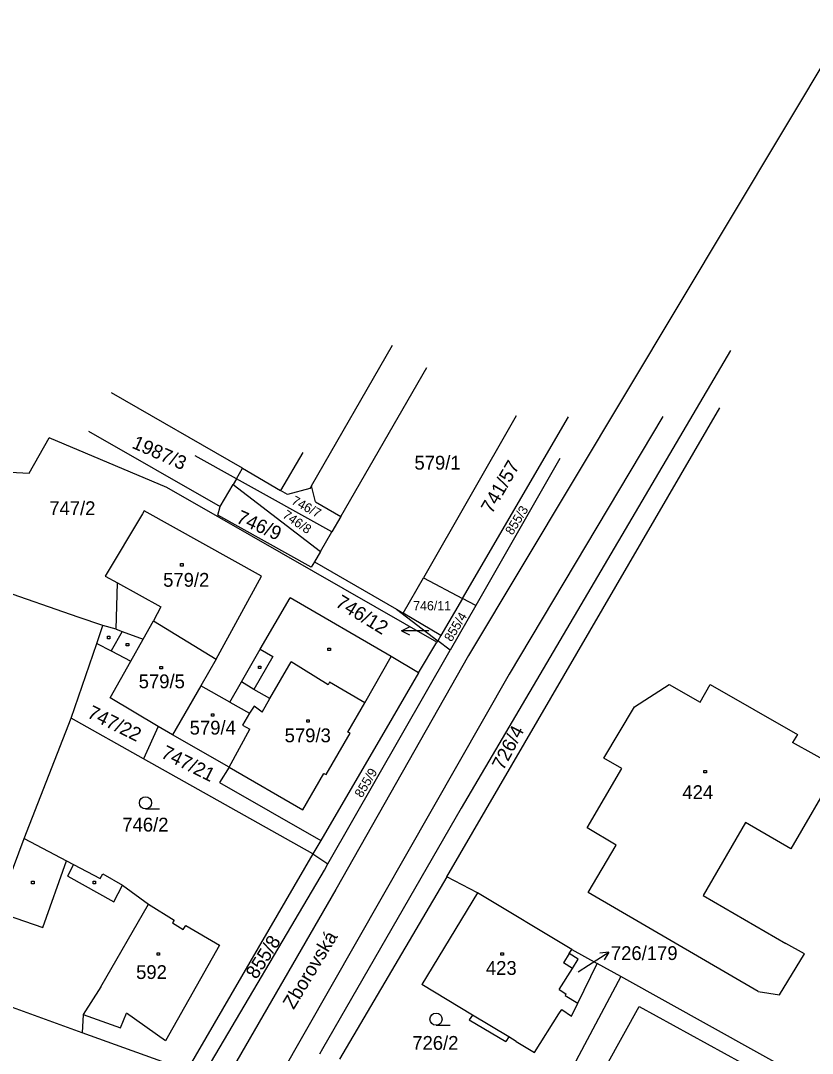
# Model space of a CAD drawing. Extents: x -711879 to -711361, y -1048782 to -1048177.
# Drawn here: x -711584.5 to -711487, y -1048304.3 to -1048177.1 of the extents above; entities that cross this region are included whole.
import ezdxf

# ---------------------------------------------------------------- set-up
doc = ezdxf.new("R2010")
doc.units = 0
for name, color, linetype in [('Vrstva 1', 7, 'Continuous'), ('Vrstva 13', 7, 'Continuous'), ('Vrstva 14', 7, 'Continuous'), ('Vrstva 15', 7, 'Continuous'), ('Vrstva 16', 7, 'Continuous'), ('Vrstva 2', 7, 'Continuous'), ('Vrstva 23', 7, 'Continuous'), ('Vrstva 25', 7, 'Continuous'), ('Vrstva 38', 7, 'Continuous'), ('Vrstva 46', 7, 'Continuous')]:
    doc.layers.add(name, color=color, linetype=linetype)

msp = doc.modelspace()

# ---------------------------------------------------------------- linework, layer by layer
at = {"layer": 'Vrstva 1'}
for p, q in [((-711482.5, -1048177.05), (-711529.35, -1048255.3)), ((-711548.71, -1048234.38), (-711538.72, -1048217.07)), ((-711497.07, -1048217.69), (-711530.26, -1048274.12)), ((-711545.09, -1048238.16), (-711534.5, -1048219.82)), ((-711557.2, -1048232.23), (-711573.32, -1048222.93)), ((-711523.47, -1048225.77), (-711534.89, -1048245.72)), ((-711532.03, -1048282.6), (-711498.38, -1048224.76)), ((-711530.09, -1048248.27), (-711517.02, -1048225.89)), ((-711505.42, -1048225.86), (-711524.36, -1048257.61)), ((-711583.46, -1048232.83), (-711581.03, -1048228.47)), ((-711566.51, -1048234.58), (-711581.03, -1048228.47)), ((-711576.16, -1048227.66), (-711559.94, -1048236.95)), ((-711557.94, -1048233.51), (-711563.01, -1048230.69)), ((-711549.75, -1048230.27), (-711552.5, -1048234.96)), ((-711518.11, -1048231.02), (-711528.46, -1048249.13)), ((-711593.81, -1048232.28), (-711583.46, -1048232.83)), ((-711557.94, -1048233.51), (-711557.2, -1048232.23)), ((-711557.2, -1048232.23), (-711552.5, -1048234.96)), ((-711557.94, -1048233.51), (-711558.36, -1048234.23)), ((-711546.19, -1048240.06), (-711557.94, -1048233.51)), ((-711559.98, -1048238.33), (-711566.51, -1048234.58)), ((-711559.94, -1048236.95), (-711558.36, -1048234.23)), ((-711558.36, -1048234.23), (-711547.58, -1048242.47)), ((-711548.91, -1048234.73), (-711551.64, -1048235.46)), ((-711548.71, -1048234.38), (-711548.91, -1048234.73)), ((-711548.21, -1048236.36), (-711548.71, -1048234.38)), ((-711551.64, -1048235.46), (-711552.5, -1048234.96)), ((-711560.23, -1048238.01), (-711559.94, -1048236.95)), ((-711548.21, -1048236.36), (-711545.09, -1048238.16)), ((-711569.52, -1048237.85), (-711574.1, -1048245.52)), ((-711569.3, -1048237.49), (-711569.52, -1048237.85)), ((-711554.84, -1048245.54), (-711569.3, -1048237.49)), ((-711548.72, -1048244.4), (-711560.23, -1048238.01)), ((-711533.26, -1048253.68), (-711559.98, -1048238.33)), ((-711545.09, -1048238.16), (-711546.19, -1048240.06)), ((-711547.58, -1048242.47), (-711546.19, -1048240.06)), ((-711547.58, -1048242.47), (-711548.33, -1048243.76)), ((-711548.33, -1048243.76), (-711548.72, -1048244.4)), ((-711548.33, -1048243.76), (-711538.23, -1048249.6)), ((-711574.1, -1048245.52), (-711572.59, -1048246.35)), ((-711560.45, -1048255.74), (-711554.84, -1048245.54)), ((-711537.39, -1048250.09), (-711534.89, -1048245.72)), ((-711534.89, -1048245.72), (-711530.09, -1048248.27)), ((-711577.43, -1048250.58), (-711587.36, -1048247.11)), ((-711572.76, -1048252.07), (-711572.59, -1048246.35)), ((-711572.59, -1048246.35), (-711567.25, -1048249.29)), ((-711555, -1048254.52), (-711551.34, -1048248.21)), ((-711538.88, -1048255.43), (-711551.34, -1048248.21)), ((-711530.09, -1048248.27), (-711532.77, -1048252.85)), ((-711528.46, -1048249.13), (-711530.09, -1048248.27)), ((-711567.25, -1048249.29), (-711568.14, -1048251.02)), ((-711538.23, -1048249.6), (-711533.14, -1048253.48)), ((-711538.23, -1048249.6), (-711537.39, -1048250.09)), ((-711532.77, -1048252.85), (-711537.39, -1048250.09)), ((-711528.46, -1048249.13), (-711531.61, -1048254.65)), ((-711574.38, -1048251.61), (-711577.43, -1048250.58)), ((-711568.14, -1048251.02), (-711560.45, -1048255.74)), ((-711575.14, -1048253.81), (-711574.38, -1048251.61)), ((-711572.76, -1048252.07), (-711574.38, -1048251.61)), ((-711578.31, -1048263.02), (-711575.14, -1048253.81)), ((-711575.14, -1048253.81), (-711573.37, -1048254.73)), ((-711535.51, -1048257.44), (-711533.26, -1048253.68)), ((-711533.14, -1048253.48), (-711533.26, -1048253.68)), ((-711532.77, -1048252.85), (-711533.14, -1048253.48)), ((-711531.61, -1048254.65), (-711533.14, -1048253.48)), ((-711573.37, -1048254.73), (-711570.94, -1048256)), ((-711557.32, -1048258.56), (-711555, -1048254.52)), ((-711546.67, -1048281), (-711531.61, -1048254.65)), ((-711573.48, -1048260.53), (-711570.94, -1048256)), ((-711560.45, -1048255.74), (-711562.34, -1048259.04)), ((-711529.35, -1048255.3), (-711545.71, -1048284.16)), ((-711535.51, -1048257.44), (-711538.88, -1048255.43)), ((-711524.36, -1048257.61), (-711555.05, -1048311.45)), ((-711535.51, -1048257.44), (-711538.77, -1048263.01)), ((-711562.34, -1048259.04), (-711565.8, -1048265.09)), ((-711558.75, -1048261.05), (-711562.34, -1048259.04)), ((-711558.75, -1048261.05), (-711557.32, -1048258.56)), ((-711508.91, -1048261.64), (-711504.62, -1048258.86)), ((-711504.62, -1048258.86), (-711500.82, -1048261.06)), ((-711500.82, -1048261.06), (-711499.56, -1048258.87)), ((-711499.56, -1048258.87), (-711488.82, -1048265.04)), ((-711567.57, -1048264.04), (-711573.48, -1048260.53)), ((-711558.75, -1048261.05), (-711556.31, -1048262.41)), ((-711556.31, -1048262.41), (-711557.2, -1048263.88)), ((-711512.66, -1048267.96), (-711508.91, -1048261.64)), ((-711584.1, -1048277.85), (-711578.31, -1048263.02)), ((-711569.39, -1048268.03), (-711578.31, -1048263.02)), ((-711567.57, -1048264.04), (-711569.39, -1048268.03)), ((-711565.8, -1048265.09), (-711567.57, -1048264.04)), ((-711557.2, -1048263.88), (-711556.28, -1048264.39)), ((-711538.77, -1048263.01), (-711547.55, -1048278.11)), ((-711558.82, -1048269.06), (-711565.8, -1048265.09)), ((-711558.82, -1048269.06), (-711556.28, -1048264.39)), ((-711488.82, -1048265.04), (-711489.42, -1048266.01)), ((-711483.84, -1048269.13), (-711489.42, -1048266.01)), ((-711510.46, -1048269.25), (-711512.66, -1048267.96)), ((-711548.53, -1048279.74), (-711569.39, -1048268.03)), ((-711558.82, -1048269.06), (-711560.01, -1048270.96)), ((-711483.84, -1048269.13), (-711489.64, -1048279.13)), ((-711514.72, -1048276.55), (-711510.46, -1048269.25)), ((-711560.01, -1048270.96), (-711547.55, -1048278.11)), ((-711530.26, -1048274.12), (-711547.33, -1048303.79)), ((-711511.14, -1048278.67), (-711514.72, -1048276.55)), ((-711495.23, -1048275.9), (-711500.44, -1048284.88)), ((-711489.64, -1048279.13), (-711495.23, -1048275.9)), ((-711586.08, -1048283.18), (-711584.1, -1048277.85)), ((-711584.1, -1048277.85), (-711578.86, -1048280.61)), ((-711547.55, -1048278.11), (-711548.53, -1048279.74)), ((-711514.6, -1048284.52), (-711511.14, -1048278.67)), ((-711578.86, -1048280.61), (-711578.03, -1048281.05)), ((-711548.53, -1048279.74), (-711564.04, -1048306.47)), ((-711548.53, -1048279.74), (-711546.67, -1048281)), ((-711578.03, -1048281.05), (-711574.74, -1048282.78)), ((-711562.07, -1048307.17), (-711547.11, -1048281.75)), ((-711547.11, -1048281.75), (-711546.67, -1048281)), ((-711574.74, -1048282.78), (-711574.4, -1048282.2)), ((-711574.4, -1048282.2), (-711571.96, -1048283.63)), ((-711532.03, -1048282.6), (-711545.23, -1048305.07)), ((-711528.23, -1048284.55), (-711532.03, -1048282.6)), ((-711571.96, -1048283.63), (-711568.78, -1048285.96)), ((-711545.71, -1048284.16), (-711558.97, -1048307.13)), ((-711528.23, -1048284.55), (-711535.11, -1048295.84)), ((-711516.63, -1048291.54), (-711528.23, -1048284.55)), ((-711493.68, -1048296.73), (-711514.6, -1048284.52)), ((-711500.44, -1048284.88), (-711490.24, -1048290.79)), ((-711568.78, -1048285.96), (-711565.61, -1048287.92)), ((-711565.61, -1048287.92), (-711565.83, -1048288.26)), ((-711565.83, -1048288.26), (-711564.51, -1048289.07)), ((-711564.51, -1048289.07), (-711564.18, -1048288.6)), ((-711564.18, -1048288.6), (-711560.01, -1048291)), ((-711487.96, -1048292.09), (-711490.24, -1048290.79)), ((-711560.01, -1048291), (-711566.67, -1048302.8)), ((-711516.95, -1048292.03), (-711516.63, -1048291.54)), ((-711515.84, -1048292.72), (-711516.95, -1048292.03)), ((-711516.63, -1048291.54), (-711513.48, -1048293.29)), ((-711491.04, -1048297.13), (-711487.96, -1048292.09)), ((-711516.55, -1048293.89), (-711515.84, -1048292.72)), ((-711515.88, -1048298.18), (-711513.48, -1048293.29)), ((-711510.59, -1048294.89), (-711513.48, -1048293.29)), ((-711518.18, -1048296.49), (-711516.55, -1048293.89)), ((-711528.87, -1048299.62), (-711535.11, -1048295.84)), ((-711510.59, -1048294.89), (-711519.58, -1048311.73)), ((-711481.7, -1048310.92), (-711510.59, -1048294.89)), ((-711576.93, -1048301.82), (-711591.11, -1048296.7)), ((-711518.18, -1048296.49), (-711517.34, -1048297.02)), ((-711517.34, -1048297.02), (-711517.46, -1048297.2)), ((-711517.46, -1048297.2), (-711515.88, -1048298.18)), ((-711493.68, -1048296.73), (-711491.04, -1048297.13)), ((-711516.65, -1048299.75), (-711515.88, -1048298.18)), ((-711576.83, -1048299.55), (-711576.93, -1048301.82)), ((-711576.83, -1048299.55), (-711572.24, -1048301.2)), ((-711572.24, -1048301.2), (-711571.49, -1048299.41)), ((-711566.67, -1048302.8), (-711571.49, -1048299.41)), ((-711528.87, -1048299.62), (-711529.27, -1048300.23)), ((-711521.23, -1048304.25), (-711518.22, -1048299.46)), ((-711518.22, -1048299.46), (-711517.86, -1048298.94)), ((-711517.86, -1048298.94), (-711516.65, -1048299.75)), ((-711529.27, -1048300.23), (-711524.77, -1048302.9)), ((-711564.04, -1048306.47), (-711576.93, -1048301.82)), ((-711524.39, -1048302.32), (-711524.77, -1048302.9)), ((-711523.49, -1048302.87), (-711524.39, -1048302.32)), ((-711523.49, -1048302.87), (-711521.23, -1048304.25)), ((-711547.33, -1048303.79), (-711547.7, -1048304.44))]:
    msp.add_line(p, q, dxfattribs=at)
msp.add_lwpolyline([(-711512.3, -1048305.77), (-711508.33, -1048298.55), (-711491.56, -1048307.79), (-711492.04, -1048308.69), (-711487.8, -1048310.99)], dxfattribs=at)
at = {"layer": 'Vrstva 13'}
for p, q in [((-711534.25, -1048252.28), (-711534.61, -1048252.28)), ((-711515.84, -1048294.28), (-711514.58, -1048293.48))]:
    msp.add_line(p, q, dxfattribs=at)
at = {"layer": 'Vrstva 16'}
for p, q in [((-711537.609, -1048252.244), (-711536.603, -1048251.756)), ((-711534.61, -1048252.28), (-711537.609, -1048252.244)), ((-711537.609, -1048252.244), (-711536.615, -1048252.756)), ((-711514.58, -1048293.48), (-711512.045, -1048291.875)), ((-711512.045, -1048291.875), (-711513.157, -1048291.987)), ((-711512.045, -1048291.875), (-711512.622, -1048292.832))]:
    msp.add_line(p, q, dxfattribs=at)
at = {"layer": 'Vrstva 2'}
for p, q in [((-711569.43, -1048253.31), (-711568.14, -1048251.02)), ((-711572.03, -1048252.34), (-711573.37, -1048254.73)), ((-711572.76, -1048252.07), (-711572.03, -1048252.34)), ((-711572.03, -1048252.34), (-711569.43, -1048253.31)), ((-711570.94, -1048256), (-711569.43, -1048253.31)), ((-711555, -1048254.52), (-711553.44, -1048255.42)), ((-711553.44, -1048255.42), (-711555.8, -1048259.48)), ((-711553.82, -1048260.62), (-711551.21, -1048256.1)), ((-711546.64, -1048258.9), (-711551.21, -1048256.1)), ((-711542.14, -1048261.13), (-711538.88, -1048255.43)), ((-711555.8, -1048259.48), (-711557.32, -1048258.56)), ((-711546.46, -1048258.59), (-711546.64, -1048258.9)), ((-711542.14, -1048261.13), (-711546.46, -1048258.59)), ((-711553.82, -1048260.62), (-711555.8, -1048259.48)), ((-711555.76, -1048261.53), (-711556.31, -1048262.41)), ((-711554.77, -1048262.27), (-711555.76, -1048261.53)), ((-711554.77, -1048262.27), (-711553.82, -1048260.62)), ((-711544.2, -1048264.74), (-711542.14, -1048261.13)), ((-711546.89, -1048269.99), (-711543.93, -1048264.89)), ((-711543.93, -1048264.89), (-711544.2, -1048264.74)), ((-711558.82, -1048269.06), (-711549.76, -1048274.32)), ((-711549.76, -1048274.32), (-711547.16, -1048269.83)), ((-711547.16, -1048269.83), (-711546.89, -1048269.99)), ((-711581.79, -1048288.85), (-711578.86, -1048280.61)), ((-711578.73, -1048282.51), (-711578.03, -1048281.05)), ((-711578.73, -1048282.51), (-711573.05, -1048285.65)), ((-711573.05, -1048285.65), (-711571.96, -1048283.63)), ((-711587.46, -1048286.88), (-711581.79, -1048288.85)), ((-711574.66, -1048296.13), (-711568.78, -1048285.96)), ((-711516.95, -1048292.03), (-711517.66, -1048293.19)), ((-711516.55, -1048293.89), (-711517.66, -1048293.19)), ((-711574.66, -1048296.13), (-711576.83, -1048299.55)), ((-711524.39, -1048302.32), (-711528.87, -1048299.62))]:
    msp.add_line(p, q, dxfattribs=at)
at = {"layer": 'Vrstva 23'}
for p, q in [((-711569.15, -1048274.22), (-711567.4, -1048274.22)), ((-711533.35, -1048300.89), (-711531.6, -1048300.89))]:
    msp.add_line(p, q, dxfattribs=at)
for centre in [(-711569.15, -1048273.47), (-711533.35, -1048300.14)]:
    msp.add_circle(centre, 0.75, dxfattribs=at)
at = {"layer": 'Vrstva 25'}
for p, q in [((-711564.82, -1048243.98), (-711564.52, -1048243.98)), ((-711564.82, -1048244.28), (-711564.82, -1048243.98)), ((-711564.52, -1048244.28), (-711564.82, -1048244.28)), ((-711564.52, -1048243.98), (-711564.52, -1048244.28)), ((-711573.82, -1048252.94), (-711573.52, -1048252.94)), ((-711573.82, -1048253.24), (-711573.82, -1048252.94)), ((-711573.52, -1048253.24), (-711573.82, -1048253.24)), ((-711573.52, -1048252.94), (-711573.52, -1048253.24)), ((-711571.51, -1048253.82), (-711571.21, -1048253.82)), ((-711571.51, -1048254.12), (-711571.51, -1048253.82)), ((-711571.21, -1048253.82), (-711571.21, -1048254.12)), ((-711571.21, -1048254.12), (-711571.51, -1048254.12)), ((-711546.66, -1048254.39), (-711546.36, -1048254.39)), ((-711546.66, -1048254.69), (-711546.66, -1048254.39)), ((-711546.36, -1048254.69), (-711546.66, -1048254.69)), ((-711546.36, -1048254.39), (-711546.36, -1048254.69)), ((-711567.36, -1048256.66), (-711567.06, -1048256.66)), ((-711567.36, -1048256.96), (-711567.36, -1048256.66)), ((-711567.06, -1048256.96), (-711567.36, -1048256.96)), ((-711567.06, -1048256.66), (-711567.06, -1048256.96)), ((-711555.22, -1048256.6), (-711554.92, -1048256.6)), ((-711555.22, -1048256.9), (-711555.22, -1048256.6)), ((-711554.92, -1048256.9), (-711555.22, -1048256.9)), ((-711554.92, -1048256.6), (-711554.92, -1048256.9)), ((-711561.01, -1048262.48), (-711560.71, -1048262.48)), ((-711561.01, -1048262.78), (-711561.01, -1048262.48)), ((-711560.71, -1048262.78), (-711561.01, -1048262.78)), ((-711560.71, -1048262.48), (-711560.71, -1048262.78)), ((-711549.28, -1048263.22), (-711548.98, -1048263.22)), ((-711549.28, -1048263.52), (-711549.28, -1048263.22)), ((-711548.98, -1048263.52), (-711549.28, -1048263.52)), ((-711548.98, -1048263.22), (-711548.98, -1048263.52)), ((-711500.35, -1048269.48), (-711500.05, -1048269.48)), ((-711500.35, -1048269.78), (-711500.35, -1048269.48)), ((-711500.05, -1048269.78), (-711500.35, -1048269.78)), ((-711500.05, -1048269.48), (-711500.05, -1048269.78)), ((-711583.17, -1048283.14), (-711582.87, -1048283.14)), ((-711583.17, -1048283.44), (-711583.17, -1048283.14)), ((-711582.87, -1048283.14), (-711582.87, -1048283.44)), ((-711575.6, -1048283.14), (-711575.3, -1048283.14)), ((-711575.6, -1048283.44), (-711575.6, -1048283.14)), ((-711575.3, -1048283.14), (-711575.3, -1048283.44)), ((-711582.87, -1048283.44), (-711583.17, -1048283.44)), ((-711575.3, -1048283.44), (-711575.6, -1048283.44)), ((-711567.72, -1048291.94), (-711567.42, -1048291.94)), ((-711567.72, -1048292.24), (-711567.72, -1048291.94)), ((-711567.42, -1048291.94), (-711567.42, -1048292.24)), ((-711525.35, -1048291.94), (-711525.05, -1048291.94)), ((-711525.35, -1048292.24), (-711525.35, -1048291.94)), ((-711525.05, -1048291.94), (-711525.05, -1048292.24)), ((-711567.42, -1048292.24), (-711567.72, -1048292.24)), ((-711525.05, -1048292.24), (-711525.35, -1048292.24))]:
    msp.add_line(p, q, dxfattribs=at)
at = {"layer": 'Vrstva 46'}
for p, q in [((-711557.2, -1048232.23), (-711557.2, -1048232.23)), ((-711583.46, -1048232.83), (-711583.46, -1048232.83)), ((-711557.94, -1048233.51), (-711557.94, -1048233.51)), ((-711566.51, -1048234.58), (-711566.51, -1048234.58)), ((-711558.36, -1048234.23), (-711558.36, -1048234.23)), ((-711548.71, -1048234.38), (-711548.71, -1048234.38)), ((-711552.5, -1048234.96), (-711552.5, -1048234.96)), ((-711559.94, -1048236.95), (-711559.94, -1048236.95)), ((-711548.21, -1048236.36), (-711548.21, -1048236.36)), ((-711569.52, -1048237.85), (-711569.52, -1048237.85)), ((-711569.3, -1048237.49), (-711569.3, -1048237.49)), ((-711559.98, -1048238.33), (-711559.98, -1048238.33)), ((-711545.09, -1048238.16), (-711545.09, -1048238.16)), ((-711546.19, -1048240.06), (-711546.19, -1048240.06)), ((-711547.58, -1048242.47), (-711547.58, -1048242.47)), ((-711548.33, -1048243.76), (-711548.33, -1048243.76)), ((-711574.1, -1048245.52), (-711574.1, -1048245.52)), ((-711554.84, -1048245.54), (-711554.84, -1048245.54)), ((-711534.89, -1048245.72), (-711534.89, -1048245.72)), ((-711551.34, -1048248.21), (-711551.34, -1048248.21)), ((-711530.09, -1048248.27), (-711530.09, -1048248.27)), ((-711567.25, -1048249.29), (-711567.25, -1048249.29)), ((-711538.23, -1048249.6), (-711538.23, -1048249.6)), ((-711537.39, -1048250.09), (-711537.39, -1048250.09)), ((-711577.43, -1048250.58), (-711577.43, -1048250.58)), ((-711568.14, -1048251.02), (-711568.14, -1048251.02)), ((-711568.14, -1048251.02), (-711568.14, -1048251.02)), ((-711574.38, -1048251.61), (-711574.38, -1048251.61)), ((-711575.14, -1048253.81), (-711575.14, -1048253.81)), ((-711533.14, -1048253.48), (-711533.14, -1048253.48)), ((-711532.77, -1048252.85), (-711532.77, -1048252.85)), ((-711555, -1048254.52), (-711555, -1048254.52)), ((-711560.57, -1048255.95), (-711560.57, -1048255.95)), ((-711560.45, -1048255.74), (-711560.45, -1048255.74)), ((-711560.33, -1048255.51), (-711560.33, -1048255.51)), ((-711538.88, -1048255.43), (-711538.88, -1048255.43)), ((-711561.07, -1048256.82), (-711561.07, -1048256.82)), ((-711556.68, -1048257.44), (-711556.68, -1048257.44)), ((-711535.51, -1048257.44), (-711535.51, -1048257.44)), ((-711562.34, -1048259.04), (-711562.34, -1048259.04)), ((-711546.64, -1048258.9), (-711546.64, -1048258.9)), ((-711546.46, -1048258.59), (-711546.46, -1048258.59)), ((-711499.56, -1048258.87), (-711499.56, -1048258.87)), ((-711555.8, -1048259.48), (-711555.8, -1048259.48)), ((-711573.48, -1048260.53), (-711573.48, -1048260.53)), ((-711573.48, -1048260.53), (-711573.48, -1048260.53)), ((-711558.75, -1048261.05), (-711558.75, -1048261.05)), ((-711555.76, -1048261.53), (-711555.76, -1048261.53)), ((-711553.82, -1048260.62), (-711553.82, -1048260.62)), ((-711542.14, -1048261.13), (-711542.14, -1048261.13)), ((-711500.82, -1048261.06), (-711500.82, -1048261.06)), ((-711556.31, -1048262.41), (-711556.31, -1048262.41)), ((-711554.77, -1048262.27), (-711554.77, -1048262.27)), ((-711578.31, -1048263.02), (-711578.31, -1048263.02)), ((-711565.8, -1048265.09), (-711565.8, -1048265.09)), ((-711565.8, -1048265.09), (-711565.8, -1048265.09)), ((-711544.2, -1048264.74), (-711544.2, -1048264.74)), ((-711543.93, -1048264.89), (-711543.93, -1048264.89)), ((-711488.82, -1048265.04), (-711488.82, -1048265.04)), ((-711558.82, -1048269.06), (-711558.82, -1048269.06)), ((-711547.16, -1048269.83), (-711547.16, -1048269.83)), ((-711546.89, -1048269.99), (-711546.89, -1048269.99)), ((-711549.76, -1048274.32), (-711549.76, -1048274.32)), ((-711514.72, -1048276.55), (-711514.72, -1048276.55)), ((-711495.23, -1048275.9), (-711495.23, -1048275.9)), ((-711584.1, -1048277.85), (-711584.1, -1048277.85)), ((-711511.14, -1048278.67), (-711511.14, -1048278.67)), ((-711489.64, -1048279.13), (-711489.64, -1048279.13)), ((-711548.53, -1048279.74), (-711548.53, -1048279.74)), ((-711546.67, -1048281), (-711546.67, -1048281)), ((-711578.73, -1048282.51), (-711578.73, -1048282.51)), ((-711532.03, -1048282.6), (-711532.03, -1048282.6)), ((-711573.05, -1048285.65), (-711573.05, -1048285.65)), ((-711528.23, -1048284.55), (-711528.23, -1048284.55)), ((-711514.6, -1048284.52), (-711514.6, -1048284.52)), ((-711500.44, -1048284.88), (-711500.44, -1048284.88)), ((-711581.79, -1048288.85), (-711581.79, -1048288.85)), ((-711490.24, -1048290.79), (-711490.24, -1048290.79)), ((-711516.63, -1048291.54), (-711516.63, -1048291.54)), ((-711487.96, -1048292.09), (-711487.96, -1048292.09)), ((-711513.48, -1048293.29), (-711513.48, -1048293.29)), ((-711516.55, -1048293.89), (-711516.55, -1048293.89)), ((-711535.11, -1048295.84), (-711535.11, -1048295.84)), ((-711510.59, -1048294.89), (-711510.59, -1048294.89)), ((-711574.66, -1048296.13), (-711574.66, -1048296.13)), ((-711518.18, -1048296.49), (-711518.18, -1048296.49)), ((-711517.34, -1048297.02), (-711517.34, -1048297.02)), ((-711493.68, -1048296.73), (-711493.68, -1048296.73)), ((-711491.04, -1048297.13), (-711491.04, -1048297.13)), ((-711576.83, -1048299.55), (-711576.83, -1048299.55)), ((-711571.49, -1048299.41), (-711571.49, -1048299.41)), ((-711518.22, -1048299.46), (-711518.22, -1048299.46)), ((-711572.24, -1048301.2), (-711572.24, -1048301.2)), ((-711523.49, -1048302.87), (-711523.49, -1048302.87)), ((-711521.23, -1048304.25), (-711521.23, -1048304.25))]:
    msp.add_line(p, q, dxfattribs=at)

# ---------------------------------------------------------------- texts
at = {"layer": 'Vrstva 14'}
for s, height, rotation, p in [('741/57', 1.7, 59.94027, (-711526.46, -1048237.93)), ('746/7', 1.14, 331.47684, (-711551.258, -1048236.563)), ('746/9', 1.7, 336.20688, (-711558.08, -1048238.87)), ('746/8', 1.14, 325.78434, (-711552.353, -1048238.231)), ('855/3', 1.14, 58.13406, (-711523.944, -1048240.547)), ('855/4', 1.14, 58.92831, (-711531.447, -1048253.691)), ('747/22', 1.7, 333.70101, (-711576.44, -1048262.89)), ('726/4', 1.7, 62.56026, (-711525.053, -1048269.566)), ('747/21', 1.7, 333.3294, (-711567.35, -1048267.81)), ('855/9', 1.14, 59.25951, (-711542.484, -1048272.922)), ('855/8', 1.7, 57.56022, (-711555.47, -1048295.31))]:
    msp.add_text(s, height=height, rotation=rotation, dxfattribs=at).set_placement(p)
for s, height, p in [('747/2', 1.7, (-711581, -1048238)), ('746/11', 1.14, (-711536.164, -1048249.74)), ('746/12', 0.1, (-711534.487, -1048252.28)), ('746/2', 1.7, (-711572, -1048277)), ('726/179', 0.1, (-711516.125, -1048294.28)), ('726/2', 1.7, (-711536.28, -1048303.91))]:
    msp.add_text(s, height=height, dxfattribs=at).set_placement(p)
at = {"layer": 'Vrstva 15'}
msp.add_text('1987/3', height=1.7, rotation=336.11346, dxfattribs=at).set_placement((-711570.93, -1048229.67))
for s, p in [('579/1', (-711536.01, -1048232.39)), ('579/2', (-711566.97, -1048246.83)), ('579/5', (-711569.98, -1048259.34)), ('579/4', (-711563.7, -1048265.05)), ('579/3', (-711552, -1048266)), ('424', (-711503, -1048273)), ('423', (-711527.21, -1048294.67)), ('592', (-711570.3, -1048295.18))]:
    msp.add_text(s, height=1.7, dxfattribs=at).set_placement(p)
at = {"layer": 'Vrstva 16'}
msp.add_text('746/12', height=1.7, rotation=328.38651, dxfattribs=at).set_placement((-711545.863, -1048249.168))
msp.add_text('726/179', height=1.7, dxfattribs=at).set_placement((-711511.81, -1048292.84))
at = {"layer": 'Vrstva 38'}
msp.add_text('Zborovská', height=1.7, rotation=58.96278, dxfattribs=at).set_placement((-711550.89, -1048299.03))

doc.saveas('drawing.dxf')
